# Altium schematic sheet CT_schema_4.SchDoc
size 278 x 236 mm
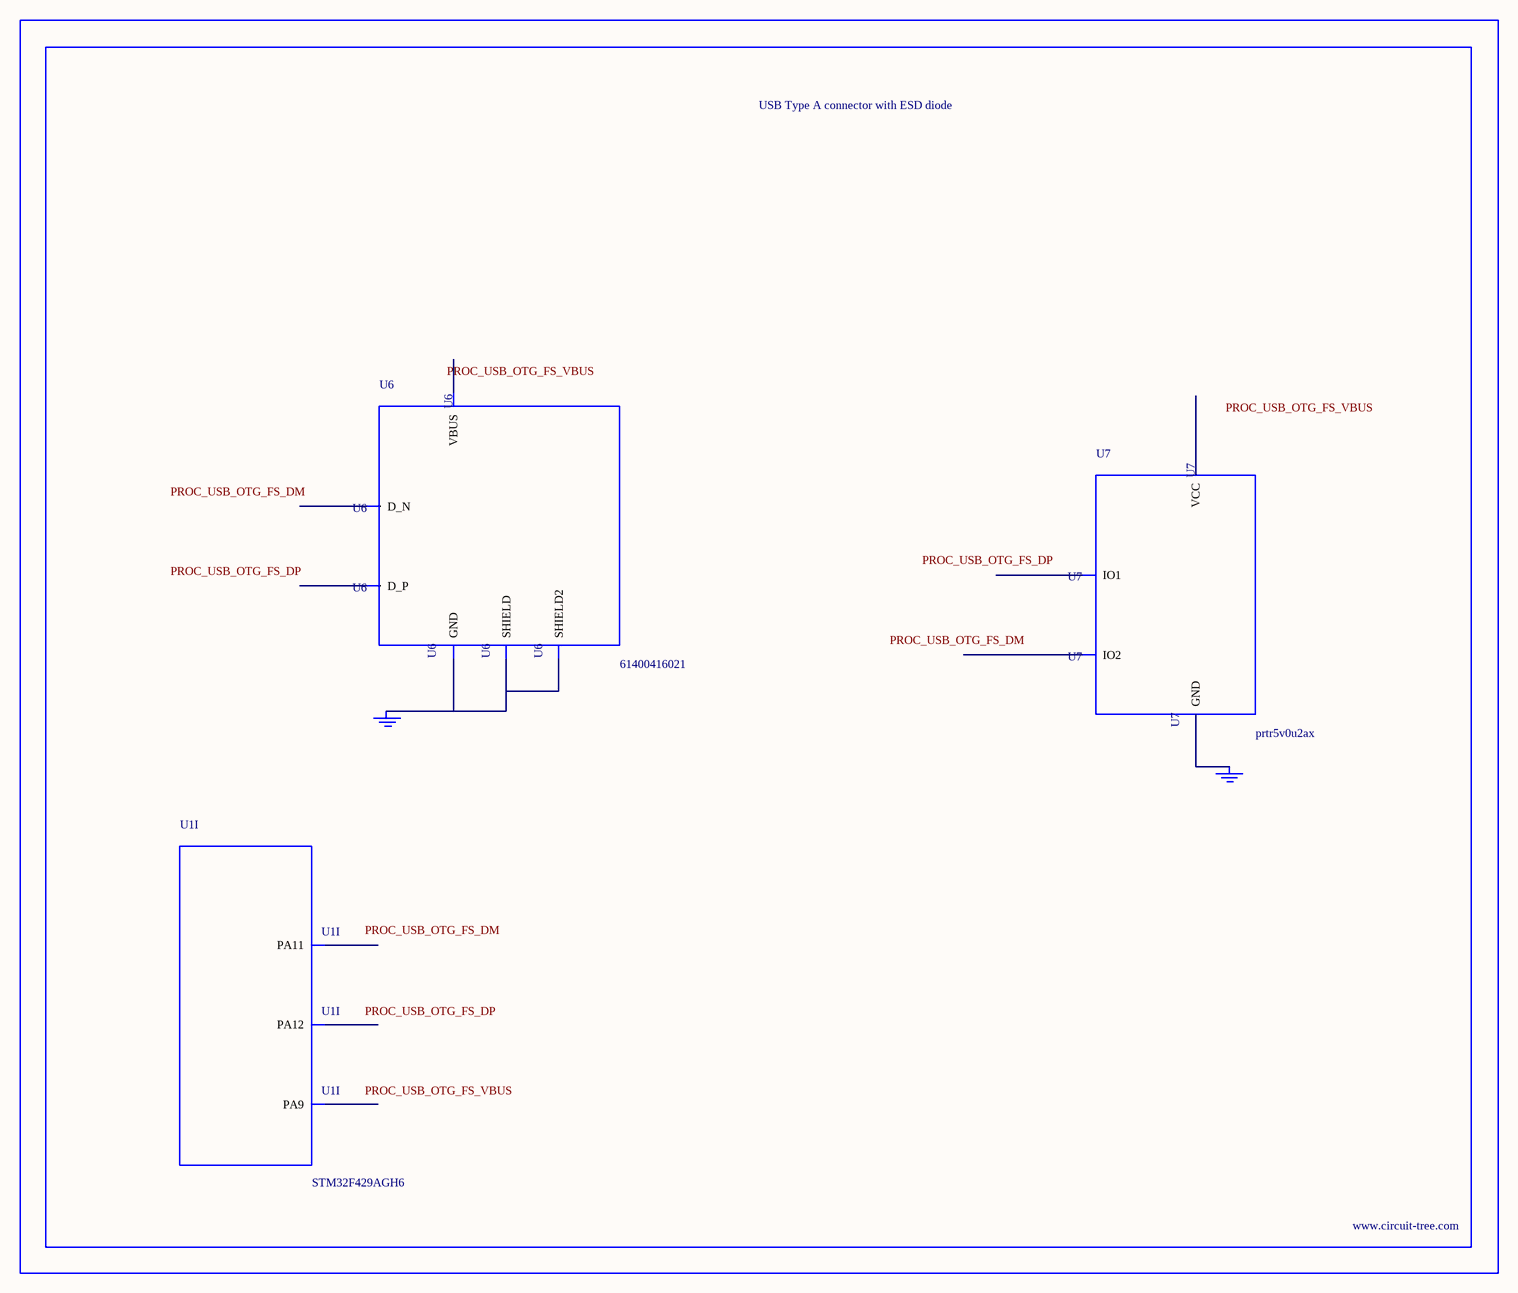
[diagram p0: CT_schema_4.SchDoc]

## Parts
BORDER3  (no value)
GND_INSTANCE_3_0  (no value)
GND_INSTANCE_3_1  (no value)
U1  STM32F429AGH6  [UFBGA169]  (part I of 11)
U6  61400416021  [USB-A-H]
U7  prtr5v0u2ax  [SOT143B]

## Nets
NetGND_INSTANCE_3_0_0: GND_INSTANCE_3_0.0(GND) U6.4(GND) U6.5(SHIELD) U6.6(SHIELD2)
NetGND_INSTANCE_3_1_0: GND_INSTANCE_3_1.0(GND) U7.1(GND)

Not connected (* = marked no-connect by the designer): U1 E8(PA9) E10(PA11) E11(PA12); U6 1(VBUS) 2(D_N) 3(D_P); U7 2(IO1) 3(IO2) 4(VCC)

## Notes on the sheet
- Labels drawn without touching a wire or pin: PROC_USB_OTG_FS_DM, PROC_USB_OTG_FS_DP, PROC_USB_OTG_FS_VBUS

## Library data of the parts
BORDER3 = BORDER_PAGE3
GND_INSTANCE_3_0 GND_INSTANCE_3_1 = GND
